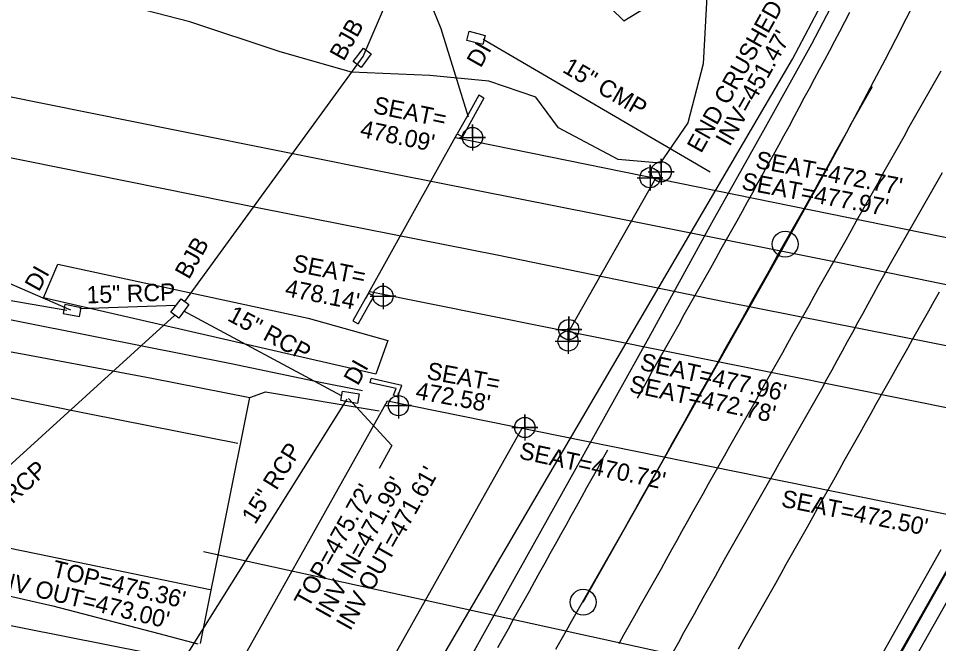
# Model space of a CAD drawing. Extents: x 2074109 to 2077820, y 741079 to 746031.
# Drawn here: x 2074752.4 to 2074966, y 742333.6 to 742478.7 of the extents above; entities that cross this region are included whole.
import ezdxf

# ---------------------------------------------------------------- set-up
doc = ezdxf.new("R2010")
doc.units = 0
for name, color, linetype in [('Exist Guardrail', 7, 'Continuous'), ('Exist Horizontal Alignment', 7, 'Continuous'), ('Exist Horizontal Alignment Point', 7, 'Continuous'), ('Exist Other Culture Fence Line', 7, 'Continuous'), ('Exist Railroads Standard Gauge', 7, 'Continuous'), ('Exist Roads Change in Surface', 7, 'Continuous'), ('Exist Roads EOP', 7, 'Continuous'), ('Exist Roads EOT', 7, 'Continuous'), ('Exist Structure Major Bridge Seam', 7, 'Continuous'), ('Exist Structure Major Bridge Seat Cogo Point CELL', 7, 'Continuous'), ('Exist Structure Major Bridge Seat Top Elevation', 7, 'Continuous'), ('Exist Structure Major Bridge WW', 7, 'Continuous'), ('Exist Structure Major Deck Tunnel Box Culvert', 7, 'Continuous'), ('Exist Structure Minor Drop Inlet', 7, 'Continuous'), ('Exist Structure Minor Drop Inlet Leader', 7, 'Continuous'), ('Exist Structure Minor Drop Inlet Text', 7, 'Continuous'), ('Exist Structure Minor Drop Inlet Top Elevation', 7, 'Continuous'), ('Exist Structure Minor Junction Box', 7, 'Continuous'), ('Exist Structure Minor Junction Box Text', 7, 'Continuous'), ('Exist Structure Minor Pipes CMP 15 Inch', 7, 'Continuous'), ('Exist Structure Minor Pipes CMP 15 Inch Invert', 7, 'Continuous'), ('Exist Structure Minor Pipes CMP 15 Inch Text', 7, 'Continuous'), ('Exist Structure Minor Pipes CMP 36 Inch', 7, 'Continuous'), ('Exist Structure Minor Pipes RCP 15 Inch', 7, 'Continuous'), ('Exist Structure Minor Pipes RCP 15 Inch Invert', 7, 'Continuous'), ('Exist Structure Minor Pipes RCP 15 Inch Text', 7, 'Continuous'), ('Exist Structure Minor Pipes RCP 24 Inch', 7, 'Continuous'), ('Exist Structure Minor Pipes RCP 24 Inch Text', 7, 'Continuous'), ('Exist Structure Minor Pipes RCP 30 Inch', 7, 'Continuous'), ('Exist Utilities Telephone UG Conduit SUE LOS C', 7, 'Continuous'), ('Exist Utilities Telephone UG FO SUE LOS B', 7, 'Continuous'), ('Exist Vegetation Woods Line', 7, 'Continuous')]:
    doc.layers.add(name, color=color, linetype=linetype)

msp = doc.modelspace()

# ---------------------------------------------------------------- linework, layer by layer
at = {"layer": 'Exist Guardrail'}
for points in [[(2074732.47, 742412.34), (2074770.28, 742404.89), (2074801.8, 742398.61), (2074821.01, 742394.56), (2074832.28, 742392.35)], [(2074792.38, 742329.47), (2074733.81, 742341.07), (2074702.85, 742347.81)]]:
    msp.add_lwpolyline(points, dxfattribs=at)
at = {"layer": 'Exist Horizontal Alignment'}
for p, q in [((2074886.11, 742205.34), (2075575.25, 743427.42)), ((2074883.5, 742343.22), (2074930.36, 742426.31))]:
    msp.add_line(p, q, dxfattribs=at)
msp.add_arc((2073693.11, 743123.99), 1420.41, 330.58124, 344.52743, dxfattribs=at)
at = {"layer": 'Exist Horizontal Alignment Point'}
for centre in [(2074930.36, 742426.31), (2074883.5, 742343.22)]:
    msp.add_circle(centre, 3, dxfattribs=at)
at = {"layer": 'Exist Other Culture Fence Line'}
msp.add_lwpolyline([(2074858.38, 742792.36), (2074854.47, 742763.81), (2074851.2, 742725.4), (2074846.04, 742674.99), (2074840.54, 742613.77), (2074836.3, 742566.7), (2074833.18, 742532.01), (2074844.04, 742496.36), (2074845.69, 742488.14), (2074850.43, 742476.33), (2074856.81, 742455.8)], dxfattribs=at)
at = {"layer": 'Exist Railroads Standard Gauge'}
for points in [[(2075238.18, 742362.14), (2075167.31, 742376.56), (2075111.68, 742387.97), (2075050.8, 742400.13), (2075002.04, 742409.86), (2074942.9, 742421.94), (2074887.18, 742433.11), (2074840, 742442.43), (2074789.1, 742452.66), (2074748.85, 742460.79)], [(2074746.57, 742447.15), (2074808.67, 742434.63), (2074863.53, 742423.83), (2074916.24, 742413), (2074972.03, 742401.94), (2075015.04, 742393.46), (2075061.38, 742384.12), (2075120.25, 742372.06), (2075177.93, 742360.24), (2075227.29, 742350.26)]]:
    msp.add_lwpolyline(points, dxfattribs=at)
at = {"layer": 'Exist Roads Change in Surface'}
msp.add_line((2074794.66, 742333.65), (2074806.12, 742390.71), dxfattribs=at)
at = {"layer": 'Exist Roads EOP'}
for points in [[(2074946.03, 742491.1), (2074936.44, 742472.71), (2074925.7, 742453.35), (2074913.24, 742431.17), (2074898.61, 742404.49), (2074883.66, 742377.59), (2074866.99, 742347.78), (2074852.89, 742322.35), (2074840.31, 742299.07), (2074831.68, 742283.69), (2074824.98, 742273.09), (2074821.75, 742269.21), (2074819.4, 742266.98), (2074817.67, 742264.47), (2074804.01, 742242.07), (2074792.81, 742223.43), (2074784.5, 742209.34), (2074779.94, 742202.91), (2074767.71, 742181.73), (2074753.23, 742154.94), (2074740.59, 742131.58)], [(2075045.28, 742485.48), (2075032.39, 742461.82), (2075017.41, 742432.2), (2075008.62, 742415.56), (2074994.4, 742390.44), (2074976.29, 742358.27), (2074960.6, 742330.46), (2074947.27, 742306.52), (2074935.38, 742284.89), (2074921.31, 742258.95), (2074908.74, 742236.47), (2074898.47, 742217.63), (2074887.04, 742193.79), (2074875.51, 742167.59), (2074863.59, 742138.18), (2074850.64, 742104.73), (2074841.42, 742081.23), (2074837.2, 742071.06), (2074833.01, 742062.28), (2074824.64, 742046.55), (2074815.15, 742028.51), (2074804.68, 742008.24), (2074793.6, 741986.73), (2074789.72, 741978.96)], [(2074726.62, 742405.68), (2074752.95, 742400.96), (2074783.43, 742395.24), (2074806.12, 742390.71)], [(2074806.12, 742390.71), (2074809.75, 742392.03), (2074836.18, 742387.65)], [(2074706.28, 742354.97), (2074732.85, 742348.64), (2074760.42, 742342.4), (2074784.99, 742335.96), (2074794.05, 742333.6)], [(2074907.49, 742250.18), (2074913.75, 742260.62), (2074920.92, 742273.46), (2074927.61, 742285.76), (2074932.44, 742294.56), (2074936.88, 742302.53), (2074942.38, 742312.35), (2074948.26, 742322.83), (2074953.82, 742332.76), (2074959.71, 742343.26), (2074966.55, 742355.42)]]:
    msp.add_lwpolyline(points, dxfattribs=at)
at = {"layer": 'Exist Roads EOT'}
for points in [[(2074945.26, 742480.03), (2074944.12, 742477.81), (2074942.98, 742475.58), (2074941.81, 742473.38), (2074940.63, 742471.18), (2074939.45, 742468.97), (2074938.27, 742466.77), (2074937.09, 742464.56), (2074935.91, 742462.36), (2074934.73, 742460.16), (2074933.55, 742457.95), (2074932.37, 742455.75), (2074931.19, 742453.55), (2074929.99, 742451.36), (2074928.78, 742449.17), (2074927.58, 742446.98), (2074926.37, 742444.79), (2074925.17, 742442.6), (2074923.97, 742440.41), (2074922.76, 742438.22), (2074921.56, 742436.03), (2074920.35, 742433.84), (2074919.14, 742431.65), (2074917.92, 742429.47), (2074916.69, 742427.29), (2074915.46, 742425.12), (2074914.24, 742422.94), (2074913.01, 742420.76), (2074911.79, 742418.58), (2074910.56, 742416.4), (2074909.33, 742414.22), (2074908.11, 742412.05), (2074906.88, 742409.87), (2074905.66, 742407.69), (2074904.43, 742405.51), (2074903.21, 742403.33), (2074901.98, 742401.15), (2074900.76, 742398.98), (2074899.53, 742396.8), (2074898.31, 742394.62), (2074897.08, 742392.44), (2074896.02, 742390.55)], [(2074966.47, 742466.46), (2074965.23, 742464.29), (2074964, 742462.12), (2074962.76, 742459.94), (2074961.53, 742457.77), (2074960.31, 742455.59), (2074959.09, 742453.41), (2074957.87, 742451.23), (2074956.64, 742449.05), (2074955.42, 742446.87), (2074954.2, 742444.69), (2074952.98, 742442.51), (2074951.75, 742440.32), (2074950.53, 742438.14), (2074949.31, 742435.96), (2074948.09, 742433.78), (2074946.86, 742431.6), (2074945.64, 742429.43), (2074944.41, 742427.25), (2074943.18, 742425.07), (2074941.95, 742422.9), (2074940.73, 742420.72), (2074939.5, 742418.54), (2074938.28, 742416.36), (2074937.05, 742414.18), (2074935.83, 742412), (2074934.6, 742409.82), (2074933.38, 742407.64), (2074932.16, 742405.46), (2074930.93, 742403.28), (2074929.71, 742401.1), (2074928.48, 742398.92), (2074927.26, 742396.74), (2074926.04, 742394.56), (2074924.82, 742392.38), (2074923.6, 742390.2), (2074922.37, 742388.02), (2074921.14, 742385.85), (2074919.91, 742383.67), (2074918.68, 742381.49), (2074917.45, 742379.32), (2074916.22, 742377.14), (2074914.99, 742374.96), (2074913.76, 742372.79), (2074912.53, 742370.61), (2074911.31, 742368.44), (2074910.08, 742366.26), (2074908.85, 742364.08), (2074907.62, 742361.9), (2074906.41, 742359.72), (2074905.2, 742357.53), (2074904, 742355.34), (2074902.77, 742353.16), (2074901.55, 742350.98), (2074900.32, 742348.8), (2074899.09, 742346.62), (2074897.87, 742344.45), (2074896.64, 742342.27), (2074895.41, 742340.09), (2074894.19, 742337.91), (2074892.96, 742335.73), (2074891.73, 742333.56)], [(2074877.13, 742332.35), (2074878.37, 742334.52), (2074879.6, 742336.7), (2074880.84, 742338.87), (2074882.08, 742341.04), (2074883.31, 742343.21), (2074884.55, 742345.39), (2074885.79, 742347.56), (2074887.02, 742349.73), (2074888.26, 742351.9), (2074889.5, 742354.07), (2074890.73, 742356.25), (2074891.97, 742358.42), (2074893.21, 742360.59), (2074894.44, 742362.77), (2074895.67, 742364.94), (2074896.9, 742367.12), (2074898.13, 742369.29), (2074899.37, 742371.47), (2074900.6, 742373.64), (2074901.82, 742375.82), (2074903.03, 742378.01), (2074904.25, 742380.19), (2074905.47, 742382.37), (2074906.68, 742384.56), (2074907.9, 742386.74), (2074909.12, 742388.92), (2074910.35, 742391.1), (2074911.58, 742393.28), (2074912.8, 742395.46), (2074914.03, 742397.63), (2074915.25, 742399.81), (2074916.47, 742401.99), (2074917.69, 742404.18), (2074918.91, 742406.36), (2074920.14, 742408.54), (2074921.36, 742410.72), (2074922.58, 742412.9), (2074923.8, 742415.08), (2074925.02, 742417.26), (2074926.24, 742419.45), (2074927.46, 742421.63), (2074928.67, 742423.81), (2074929.89, 742425.99), (2074931.13, 742428.16), (2074932.36, 742430.34), (2074933.6, 742432.51), (2074934.83, 742434.68), (2074936.07, 742436.86), (2074937.3, 742439.03), (2074938.51, 742441.22), (2074939.72, 742443.41), (2074940.93, 742445.59), (2074942.14, 742447.78), (2074943.35, 742449.97), (2074944.56, 742452.15), (2074945.78, 742454.34), (2074947.01, 742456.51), (2074948.23, 742458.69), (2074949.46, 742460.87), (2074950.59, 742462.89)], [(2074904.43, 742331.81), (2074905.65, 742333.99), (2074906.87, 742336.17), (2074908.08, 742338.36), (2074909.3, 742340.54), (2074910.52, 742342.72), (2074911.74, 742344.9), (2074912.96, 742347.09), (2074914.18, 742349.27), (2074915.39, 742351.45), (2074916.61, 742353.64), (2074917.82, 742355.82), (2074919.04, 742358.01), (2074920.28, 742360.18), (2074921.52, 742362.35), (2074922.76, 742364.52), (2074924, 742366.69), (2074925.24, 742368.86), (2074926.48, 742371.03), (2074927.72, 742373.2), (2074928.96, 742375.37), (2074930.2, 742377.54), (2074931.44, 742379.71), (2074932.68, 742381.88), (2074933.92, 742384.05), (2074935.15, 742386.23), (2074936.39, 742388.4), (2074937.63, 742390.57), (2074938.85, 742392.75), (2074940.05, 742394.94), (2074941.25, 742397.14), (2074942.45, 742399.33), (2074943.65, 742401.52), (2074944.85, 742403.72), (2074946.05, 742405.91), (2074947.25, 742408.1), (2074948.45, 742410.29), (2074949.65, 742412.49), (2074950.85, 742414.68), (2074952.05, 742416.87), (2074953.26, 742419.06), (2074954.49, 742421.24), (2074955.72, 742423.41), (2074956.95, 742425.59), (2074958.19, 742427.76), (2074959.43, 742429.93), (2074960.68, 742432.1), (2074961.92, 742434.27), (2074963.16, 742436.44), (2074964.4, 742438.61), (2074965.64, 742440.78), (2074966.88, 742442.95)], [(2074966.09, 742415.13), (2074964.86, 742412.96), (2074963.63, 742410.78), (2074962.4, 742408.6), (2074961.17, 742406.43), (2074959.94, 742404.25), (2074958.71, 742402.08), (2074957.48, 742399.9), (2074956.25, 742397.72), (2074955.02, 742395.54), (2074953.8, 742393.37), (2074952.58, 742391.19), (2074951.35, 742389.01), (2074950.13, 742386.83), (2074948.9, 742384.65), (2074947.68, 742382.47), (2074946.46, 742380.29), (2074945.23, 742378.11), (2074944.01, 742375.93), (2074942.78, 742373.75), (2074941.56, 742371.57), (2074940.34, 742369.39), (2074939.11, 742367.21), (2074937.89, 742365.03), (2074936.67, 742362.85), (2074935.44, 742360.67), (2074934.22, 742358.49), (2074932.99, 742356.31), (2074931.77, 742354.13), (2074930.55, 742351.95), (2074929.32, 742349.78), (2074928.09, 742347.6), (2074926.86, 742345.42), (2074925.63, 742343.24), (2074924.4, 742341.07), (2074923.17, 742338.89), (2074921.95, 742336.71), (2074920.72, 742334.54), (2074919.49, 742332.36)], [(2074724.27, 742395.91), (2074768.94, 742386.91), (2074803.38, 742380.14)], [(2074889.12, 742378.51), (2074887.91, 742376.32), (2074886.7, 742374.13), (2074885.49, 742371.94), (2074884.28, 742369.76), (2074883.07, 742367.57), (2074881.86, 742365.38), (2074880.65, 742363.19), (2074879.44, 742361.01), (2074878.22, 742358.83), (2074877.01, 742356.64), (2074875.79, 742354.46), (2074874.57, 742352.28), (2074873.36, 742350.09), (2074872.14, 742347.91), (2074870.92, 742345.73), (2074869.71, 742343.54), (2074868.49, 742341.36), (2074867.27, 742339.18), (2074866.06, 742336.99), (2074864.85, 742334.81), (2074863.64, 742332.62)], [(2074710.45, 742363.95), (2074759.61, 742353.88), (2074796.91, 742346.2)]]:
    msp.add_lwpolyline(points, dxfattribs=at)
at = {"layer": 'Exist Structure Major Bridge Seam'}
for p, q in [((2074880.13, 742406.03), (2074900.36, 742441.59)), ((2074834.17, 742321.15), (2074869.36, 742383.61)), ((2074939.06, 742299.88), (2074974.45, 742362.3))]:
    msp.add_line(p, q, dxfattribs=at)
at = {"layer": 'Exist Structure Major Bridge Seat Cogo Point CELL'}
for points in [[(2074854.8, 742451.04), (2074860.8, 742451.04), (2074857.8, 742451.04), (2074857.8, 742454.04), (2074857.8, 742448.04)], [(2074898.6, 742443.08), (2074904.6, 742443.08), (2074901.6, 742443.08), (2074901.6, 742446.08), (2074901.6, 742440.08)], [(2074896, 742441.71), (2074902, 742441.71), (2074899, 742441.71), (2074899, 742444.71), (2074899, 742438.71)], [(2074834.04, 742414.23), (2074840.04, 742414.23), (2074837.04, 742414.23), (2074837.04, 742417.23), (2074837.04, 742411.23)], [(2074877.14, 742406.48), (2074883.14, 742406.48), (2074880.14, 742406.48), (2074880.14, 742409.48), (2074880.14, 742403.48)], [(2074876.98, 742403.82), (2074882.98, 742403.82), (2074879.98, 742403.82), (2074879.98, 742406.82), (2074879.98, 742400.82)], [(2074837.62, 742388.83), (2074843.62, 742388.83), (2074840.62, 742388.83), (2074840.62, 742391.83), (2074840.62, 742385.83)], [(2074866.95, 742383.77), (2074872.95, 742383.77), (2074869.95, 742383.77), (2074869.95, 742386.77), (2074869.95, 742380.77)]]:
    msp.add_lwpolyline(points, dxfattribs=at)
for centre in [(2074857.8, 742451.04), (2074901.6, 742443.08), (2074899, 742441.71), (2074837.04, 742414.23), (2074880.14, 742406.48), (2074879.98, 742403.82), (2074840.62, 742388.83), (2074869.95, 742383.77)]:
    msp.add_circle(centre, 2.34, dxfattribs=at)
at = {"layer": 'Exist Structure Major Bridge WW'}
for points in [[(2074860.45, 742460.17), (2074859.26, 742460.83), (2074856.39, 742455.65), (2074854.28, 742451.89), (2074855.47, 742451.23)], [(2074860.45, 742460.17), (2074857.58, 742454.99), (2074855.47, 742451.23)], [(2074833.71, 742414.89), (2074854.28, 742451.89)], [(2074834.88, 742414.2), (2074833.71, 742414.89), (2074832.93, 742413.59), (2074830.05, 742408.5), (2074831.24, 742407.83)], [(2074834.88, 742414.2), (2074834.11, 742412.9), (2074831.24, 742407.83)], [(2074839.44, 742391.23), (2074840.06, 742392.79), (2074834.08, 742394.16), (2074834.3, 742395.14)], [(2074839.44, 742391.23), (2074840.37, 742390.86), (2074841.42, 742393.5), (2074834.3, 742395.14)]]:
    msp.add_lwpolyline(points, dxfattribs=at)
at = {"layer": 'Exist Structure Major Deck Tunnel Box Culvert'}
for p, q in [((2074853.83, 742451.08), (2075190.32, 742382.44)), ((2074833.95, 742415.32), (2075170.73, 742347.6)), ((2074803.05, 742327.46), (2074838.09, 742389.96)), ((2074838.09, 742389.96), (2075141.11, 742328.49))]:
    msp.add_line(p, q, dxfattribs=at)
at = {"layer": 'Exist Structure Minor Drop Inlet'}
for points in [[(2074857.07, 742475.7), (2074860.78, 742474.73), (2074860.23, 742472.61), (2074856.52, 742473.58)], [(2074762.82, 742410.23), (2074766.59, 742409.52), (2074766.97, 742411.56), (2074763.2, 742412.26)], [(2074831.11, 742389.36), (2074827.24, 742390.04), (2074827.62, 742392.21), (2074831.48, 742391.54)]]:
    msp.add_lwpolyline(points, close=True, dxfattribs=at)
at = {"layer": 'Exist Structure Minor Drop Inlet Leader'}
for points in [[(2074764.64, 742411.01), (2074719.79, 742430.41), (2074723.15, 742436.4)], [(2074829.02, 742390.5), (2074839.12, 742379.59), (2074836.14, 742374.28)]]:
    msp.add_lwpolyline(points, dxfattribs=at)
at = {"layer": 'Exist Structure Minor Junction Box'}
for points in [[(2074830.15, 742468.65), (2074832.49, 742471.78), (2074834.29, 742470.44), (2074831.95, 742467.3)], [(2074787.83, 742410.51), (2074790.17, 742413.65), (2074791.97, 742412.3), (2074789.63, 742409.16)]]:
    msp.add_lwpolyline(points, close=True, dxfattribs=at)
at = {"layer": 'Exist Structure Minor Pipes CMP 15 Inch'}
msp.add_line((2074912.94, 742442.97), (2074860.32, 742473.77), dxfattribs=at)
at = {"layer": 'Exist Structure Minor Pipes CMP 36 Inch'}
msp.add_line((2074832.42, 742469.8), (2074887.73, 742599.54), dxfattribs=at)
at = {"layer": 'Exist Structure Minor Pipes RCP 15 Inch'}
for p, q in [((2074763.68, 742410.89), (2074640.4, 742432.41)), ((2074789, 742412.08), (2074766.72, 742411.29)), ((2074827.43, 742391.13), (2074790.8, 742410.73)), ((2074791.83, 742331.49), (2074828.7, 742390.33))]:
    msp.add_line(p, q, dxfattribs=at)
at = {"layer": 'Exist Structure Minor Pipes RCP 24 Inch'}
msp.add_line((2074788.73, 742409.84), (2074647.3, 742281.28), dxfattribs=at)
at = {"layer": 'Exist Structure Minor Pipes RCP 30 Inch'}
msp.add_line((2074791.07, 742412.97), (2074832.42, 742469.8), dxfattribs=at)
at = {"layer": 'Exist Utilities Telephone UG Conduit SUE LOS C'}
msp.add_line((2074795.36, 742355.02), (2075175.89, 742271.74), dxfattribs=at)
at = {"layer": 'Exist Utilities Telephone UG FO SUE LOS B'}
msp.add_lwpolyline([(2074677.89, 742048.45), (2074687.56, 742064.31), (2074720.62, 742125.71), (2074754.72, 742174.31), (2074761.25, 742192.2), (2074789.79, 742226.39), (2074932.06, 742469.18), (2074970.24, 742541.68)], dxfattribs=at)
at = {"layer": 'Exist Vegetation Woods Line'}
for points in [[(2074890.02, 742480.95), (2074892.93, 742478.14), (2074906.79, 742486.64)], [(2074912.26, 742485.29), (2074911.37, 742468.14), (2074907.76, 742454.41), (2074901.37, 742445.1), (2074891.64, 742445.96), (2074877.79, 742453.3), (2074872.5, 742460.42), (2074861.59, 742464.15), (2074847.88, 742465.45), (2074829.73, 742466.17), (2074813.17, 742470.88), (2074792.21, 742477.86), (2074773.87, 742482.58)], [(2074761.55, 742421.68), (2074819.67, 742409.15), (2074838.15, 742403.91), (2074835.4, 742396.16), (2074758.24, 742413.88), (2074761.55, 742421.68)]]:
    msp.add_lwpolyline(points, dxfattribs=at)

# ---------------------------------------------------------------- texts
at = {"layer": 'Exist Structure Major Bridge Seat Top Elevation'}
for s, rotation, p in [('SEAT=', 348.406, (2074834.55, 742456.74)), ("478.09'", 348.406, (2074831.52, 742451.23)), ("SEAT=472.77'", 349.3205, (2074923.27, 742444.03)), ("SEAT=477.97'", 349.4879, (2074920.04, 742439.07)), ('SEAT=', 348.7902, (2074815.81, 742420.07)), ("478.14'", 348.7902, (2074814.09, 742414.3)), ("SEAT=477.96'", 347.5679, (2074896.46, 742397.21)), ('SEAT=', 349.6038, (2074846.99, 742395.07)), ("472.58'", 349.6038, (2074844.41, 742390.45)), ("SEAT=472.78'", 347.8758, (2074893.97, 742392.06)), ("SEAT=470.72'", 347.8984, (2074868.41, 742376.59)), ("SEAT=472.50'", 348.6342, (2074929.24, 742365.45))]:
    msp.add_text(s, height=4, rotation=rotation, dxfattribs=at).set_placement(p)
at = {"layer": 'Exist Structure Minor Drop Inlet Text'}
for p in [(2074859.72, 742467.01), (2074757.17, 742415.06), (2074831.19, 742393.27)]:
    msp.add_text('DI', height=4, rotation=60.7411, dxfattribs=at).set_placement(p)
at = {"layer": 'Exist Structure Minor Drop Inlet Top Elevation'}
for s, rotation, p in [("TOP=475.72'", 60.7411, (2074819.7, 742341.68)), ("TOP=475.36'", 346.3943, (2074760.04, 742349.16))]:
    msp.add_text(s, height=4, rotation=rotation, dxfattribs=at).set_placement(p)
at = {"layer": 'Exist Structure Minor Junction Box Text'}
for p in [(2074827.92, 742468.57), (2074792.01, 742417.92)]:
    msp.add_text('BJB', height=4, rotation=60.7411, dxfattribs=at).set_placement(p)
at = {"layer": 'Exist Structure Minor Pipes CMP 15 Inch Invert'}
for s, p in [('END CRUSHED', (2074910.85, 742447.2)), ("INV=451.47'", (2074917.47, 742448.76))]:
    msp.add_text(s, height=4, rotation=60.742, dxfattribs=at).set_placement(p)
at = {"layer": 'Exist Structure Minor Pipes CMP 15 Inch Text'}
msp.add_text('15" CMP', height=4, rotation=329.6585, dxfattribs=at).set_placement((2074878.45, 742466.35))
at = {"layer": 'Exist Structure Minor Pipes RCP 15 Inch Invert'}
for s, rotation, p in [("INV OUT=471.61'", 60.7411, (2074829.43, 742336.42)), ("INV IN=471.99'", 60.7411, (2074824.59, 742339.22)), ("INV OUT=473.00'", 346.3943, (2074745.91, 742347.01))]:
    msp.add_text(s, height=4, rotation=rotation, dxfattribs=at).set_placement(p)
at = {"layer": 'Exist Structure Minor Pipes RCP 15 Inch Text'}
for rotation, p in [(2.021, (2074768.31, 742412.53)), (331.84, (2074800.71, 742408.7)), (57.9274, (2074807.36, 742361.09))]:
    msp.add_text('15" RCP', height=4, rotation=rotation, dxfattribs=at).set_placement(p)
at = {"layer": 'Exist Structure Minor Pipes RCP 24 Inch Text'}
msp.add_text('24" RCP', height=4, rotation=42.2696, dxfattribs=at).set_placement((2074744.14, 742359.58))

doc.saveas('drawing.dxf')
